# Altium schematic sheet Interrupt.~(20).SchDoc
size A; SheetNumber: 1; SheetTotal: 1
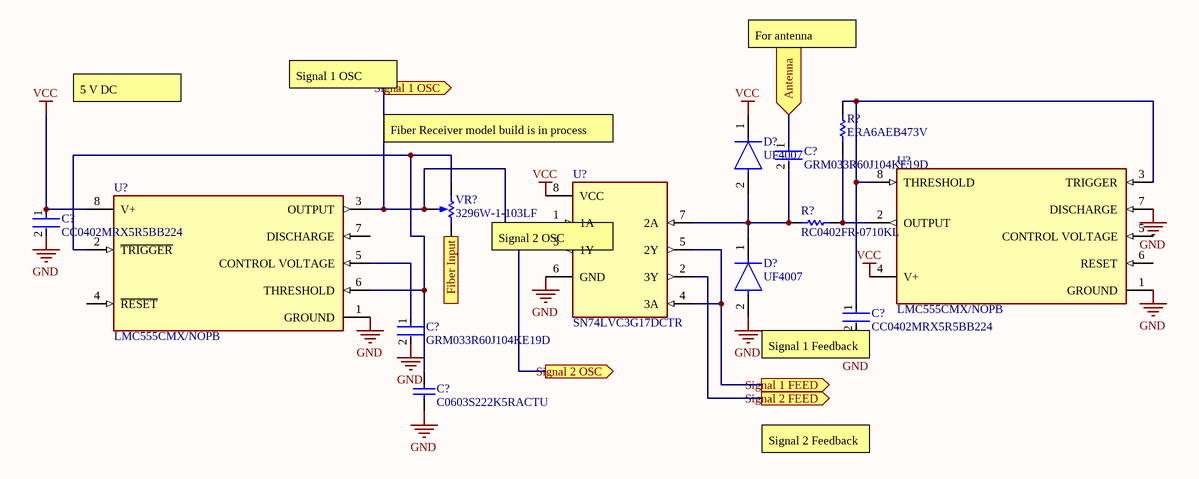
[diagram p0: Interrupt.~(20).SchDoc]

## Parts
(Parts that share a designator on the sheet are numbered #1, #2 ... from top to bottom, then left to right.)
C?#1  GRM033R60J104KE19D  [FP-GRM033-0_03-MFG]
C?#2  CC0402MRX5R5BB224  [FP-CC0402-MFG]
C?#3  CC0402MRX5R5BB224  [FP-CC0402-MFG]
C?#4  GRM033R60J104KE19D  [FP-GRM033-0_03-MFG]
C?#5  C0603S222K5RACTU  [CAPC1608X87X35NL15T15]
D?#1  UF4007  [FP-017AH-MFG]
D?#2  UF4007  [FP-017AH-MFG]
R?#1  ERA6AEB473V  [RESC2013X60X40LL20T25]
R?#2  RC0402FR-0710KL  [RESC1005X40X25LL05T10]
U?#1  LMC555CMX/NOPB  [FP-D0008A-MFG]
U?#2  SN74LVC3G17DCTR  [FP-DCT0008A-MFG]
U?#3  LMC555CMX/NOPB  [FP-D0008A-MFG]
VR?  3296W-1-103LF  [BOUR-3296W]

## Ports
Antenna (in), Fiber Input (in), Signal 1 FEED (out), Signal 1 OSC (out), Signal 2 FEED (out), Signal 2 OSC (out)

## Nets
GND: C?#2.2 C?#3.2 C?#4.2 C?#5.1 D?#2.2(A) U?#1.1(GROUND) U?#1.7(DISCHARGE) U?#2.6(GND) U?#3.1(GROUND)
VCC: C?#2.1 D?#1.1(C) U?#1.4(V+) U?#2.8(VCC) U?#3.8(V+)
Antenna: C?#1.1 ; port Antenna
Fiber Input: VR?.3(CW) ; port Fiber Input
Signal 1 FEED: U?#2.4(3A) U?#2.5(2Y) ; port Signal 1 FEED
Signal 1 OSC: U?#2.1(1A) U?#3.3(OUTPUT) VR?.2(S) ; port Signal 1 OSC
Signal 2 FEED: U?#2.2(3Y) ; port Signal 2 FEED
Signal 2 OSC: U?#2.3(1Y) ; port Signal 2 OSC
NetC?#1_2: C?#1.2 D?#1.2(A) D?#2.1(C) R?#2.1 U?#2.7(2A)
NetC?#3_1: C?#3.1 R?#1.2 U?#1.3(TRIGGER) U?#1.8(THRESHOLD)
NetC?#4_1: C?#4.1 U?#3.5(CONTROL_VOLTAGE)
NetC?#5_2: C?#5.2 U?#3.2(~{TRIGGER}) U?#3.6(THRESHOLD) VR?.1(CCW)
NetR?#1_1: R?#1.1 R?#2.2 U?#1.2(OUTPUT)

Not connected (* = marked no-connect by the designer): U?#1 5(CONTROL_VOLTAGE) 6(RESET); U?#3 4(~{RESET}) 7(DISCHARGE)

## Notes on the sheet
- For antenna
- 5 V DC
- Signal 1 OSC
- Fiber Receiver model build is in process
- (near U?#2) Signal 2 OSC
  Inverted signal output
- (near C?#3) Signal 1 Feedback
  (inverted)
- Signal 2 Feedback

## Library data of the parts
C?#1 = CMP-06035-000062-2: Chip Multilayer Ceramic Capacitors for General Purpose, 0201, 0.10uF, X5R, 15%, 10%, 6.3V; Capacitance: 100nF
C?#2 C?#3 = CMP-03422-000657-1: CAP CER 0.22UF 6.3V X5R 0402; Manufacturer: YAGEO; Automotive Grade: NA; Material: Ceramic; Value: 220 nF; Tolerance: 0.2; Temperature Coefficient: 30ppm/°C
C?#4 = CMP-06035-000062-2: 100 nF Chip Multilayer Ceramic Capacitors for General Purpose, 0201, 0.10uF, X5R, 15%, 10%, 6.3V; Capacitance: 100nF
C?#5 = CMP-2006-03289-1: Manufacturer: Kemet
D?#1 D?#2 = CMP-2000-05028-2: DIODE GEN PURP 1KV 1A DO41; Manufacturer: ON Semiconductor; Capacitance: 17pF; Max Surge Forward Current: 30A; Max Repetitive Reverse Voltage: 1000V; Value: 17pF; Max Junction Temp: +150°C; Peak Reverse Current: 10uA
R?#1 = CMP-2001-00645-1: Manufacturer: Panasonic
R?#2 = CMP-2002-07353-1: 10Kohm; Manufacturer: Yageo / Phycomp
U?#1 U?#3 = CMP-04858-000001-1: IC OSC SINGLE TIMER 3MHZ 8-SOIC; Manufacturer: Texas Instruments; Number Of Timers/Counters: 1; Max Supply Voltage: 15V; Standoff Height: 0.11mm; Propagation Delay: 100ns; Nominal Supply Current: 50-150uA; Min Supply Voltage: 1.5V
U?#2 = CMP-0859-00525-5: IC BUFFER NON-INVERT 5.5V SM8; Manufacturer: Texas Instruments; Logic Function Desc: Non-Inverting; Propagation Delay: 5.1ns; Number Of Inputs: 3; Standoff Height: 0mm; Nominal Supply Current: 10uA; Min Supply Voltage: 1.65V
VR? = CMP-1747-00001-1: Square Trimpot(R) Trimming Potentiometer, 10 KOhm, +/- 10%, 0.5 W, -55 to 125 degC, 3-Pin THD, RoHS, Tube; Voltage Rating: 75 V; Resistance: 120 Ohm; Tolerance: 1%; Power Rating: 100 mW; Case\Package: 0603; Type (Resistor): Thick Film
